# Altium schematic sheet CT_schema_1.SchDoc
size 690 x 636 mm
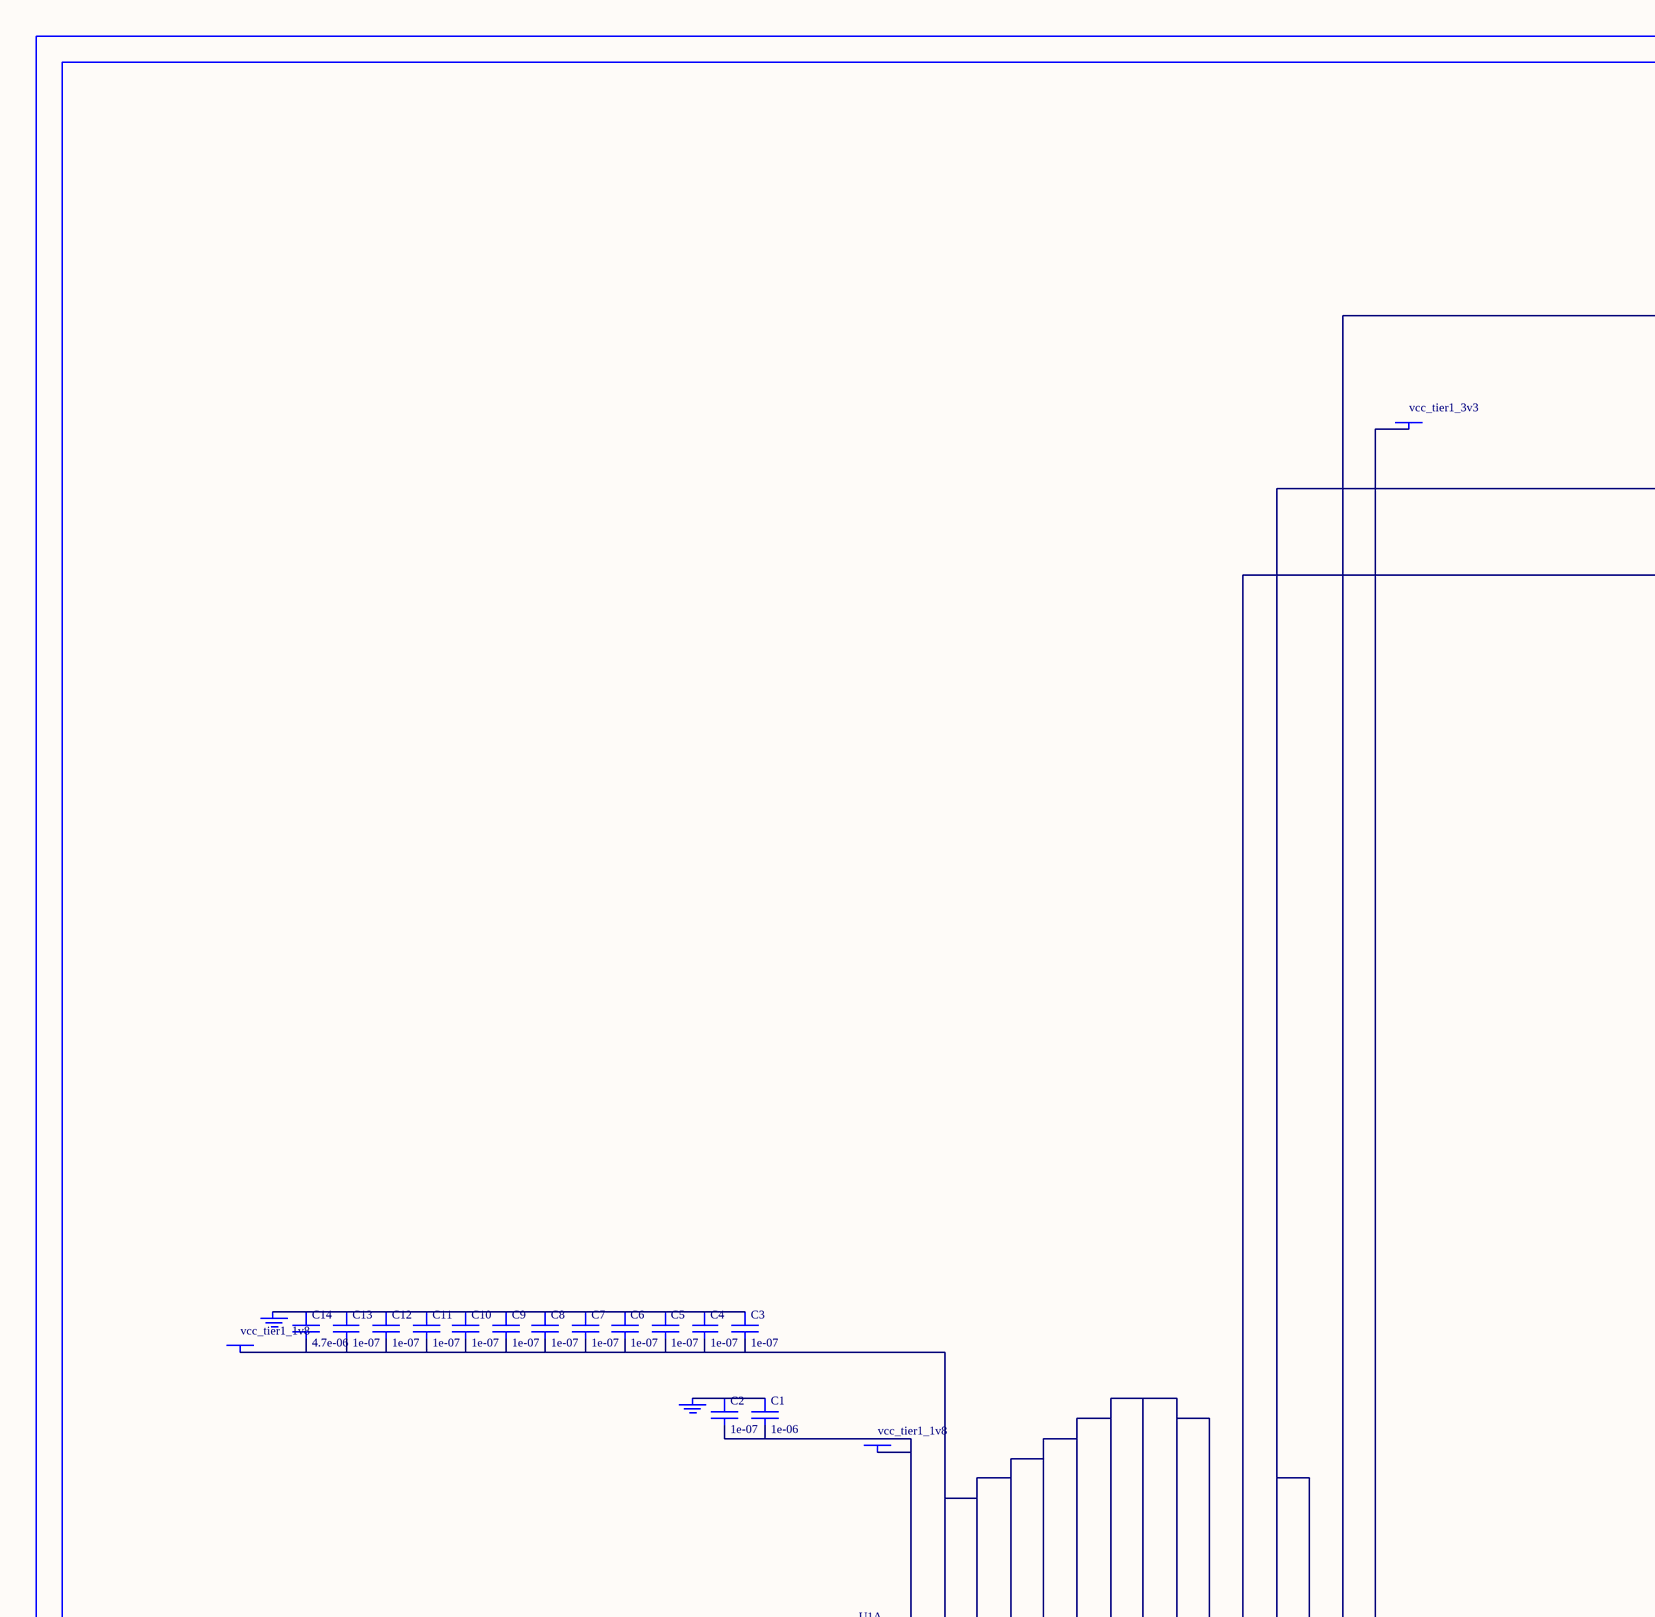
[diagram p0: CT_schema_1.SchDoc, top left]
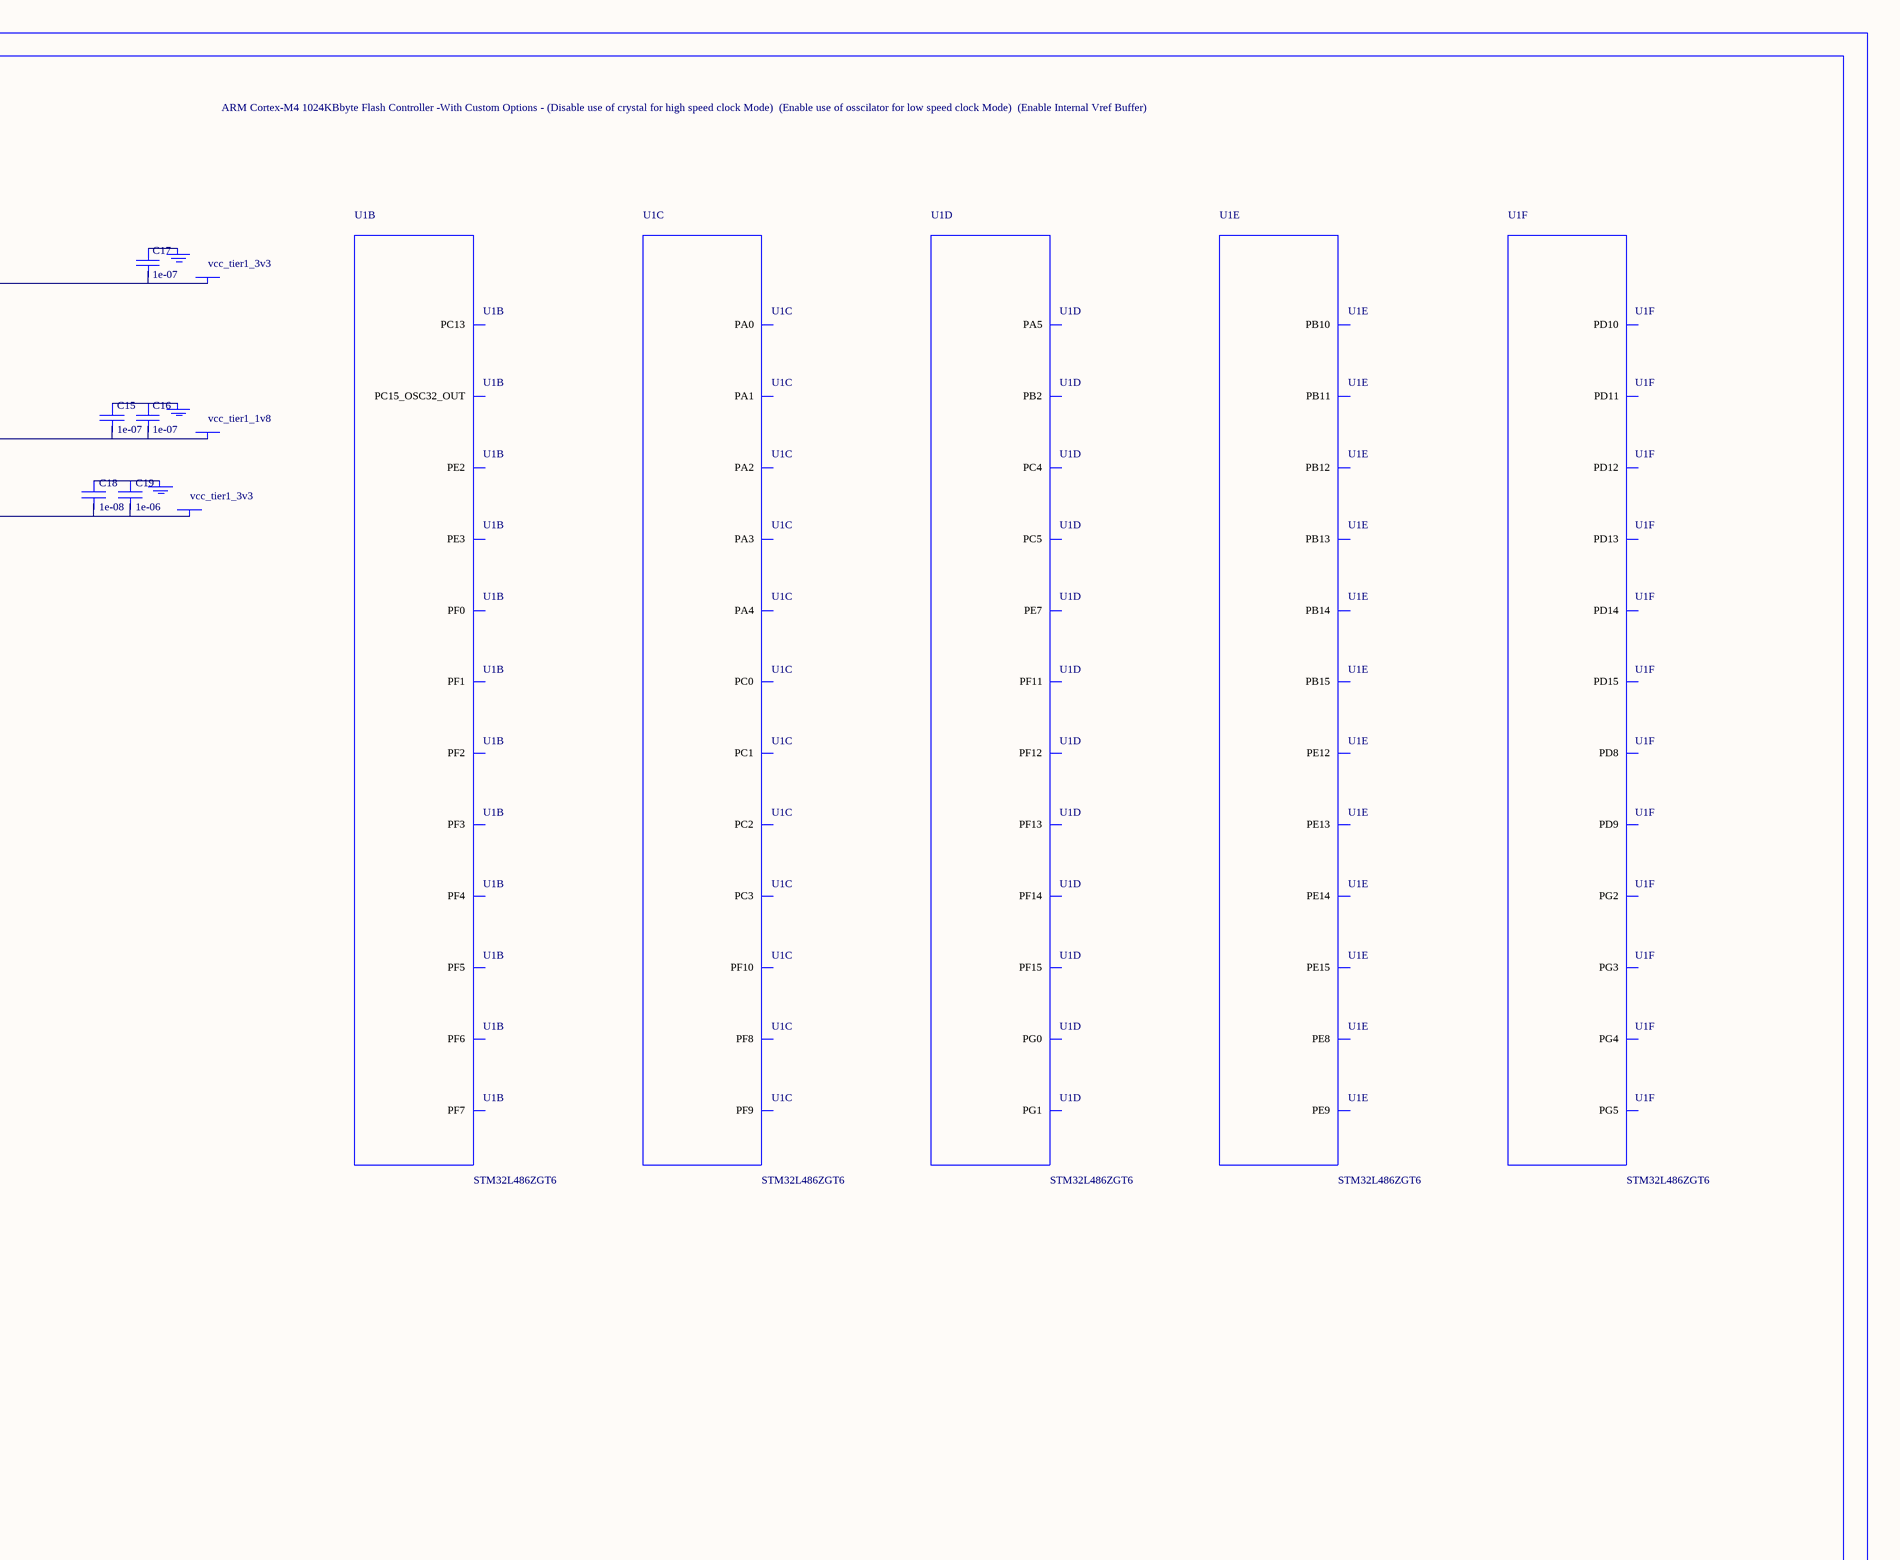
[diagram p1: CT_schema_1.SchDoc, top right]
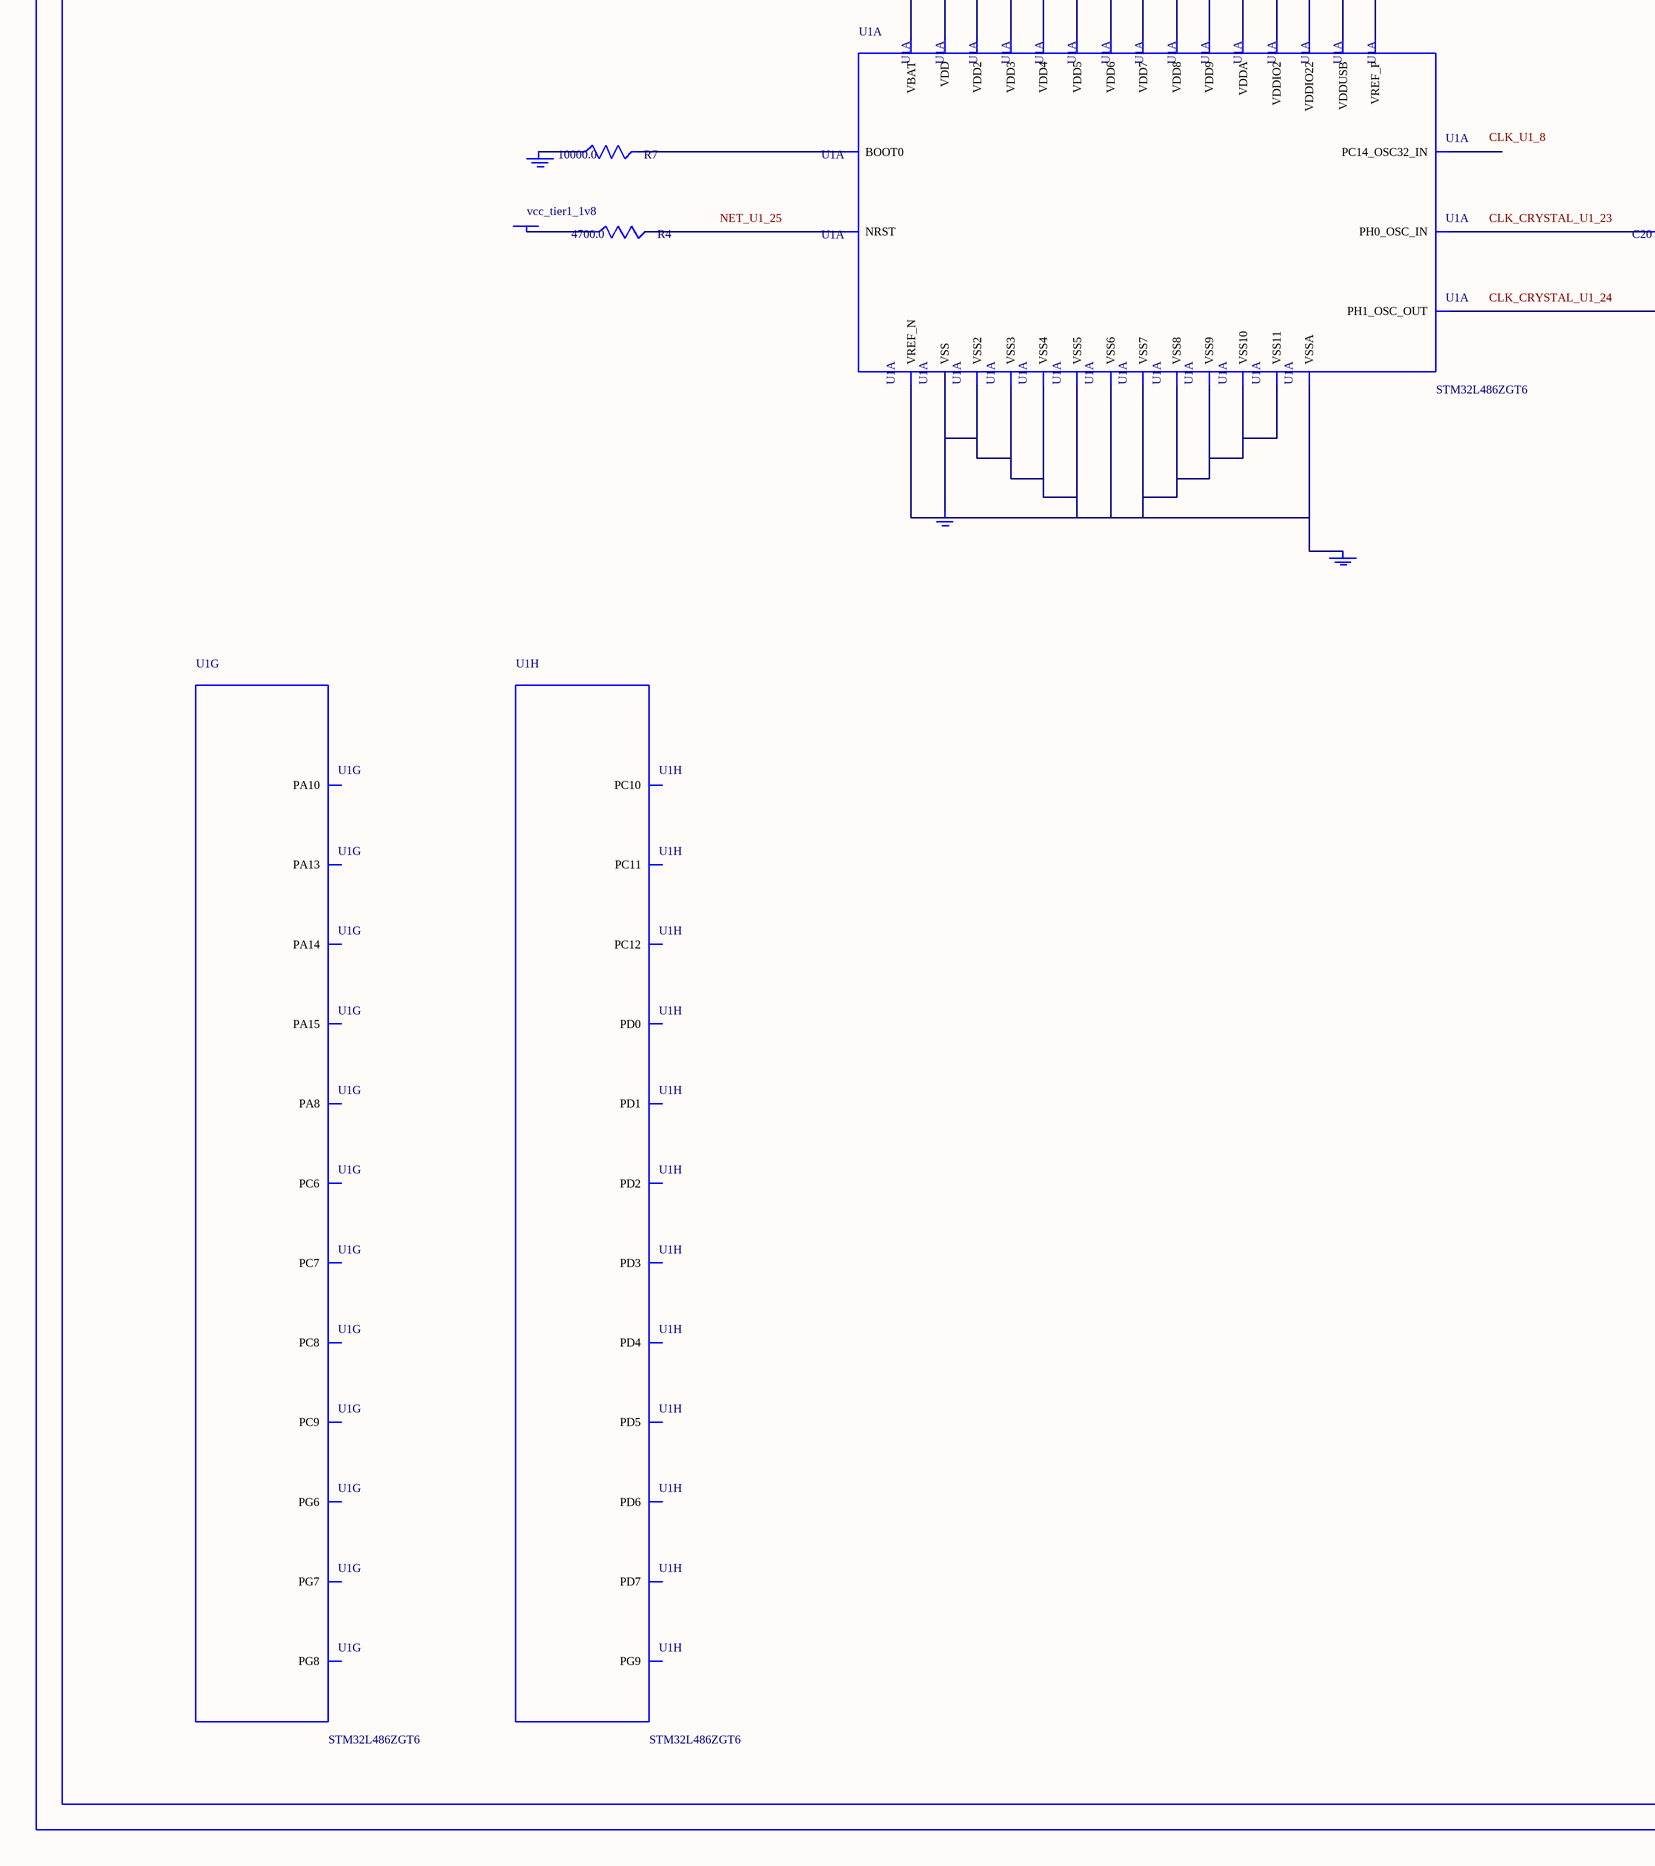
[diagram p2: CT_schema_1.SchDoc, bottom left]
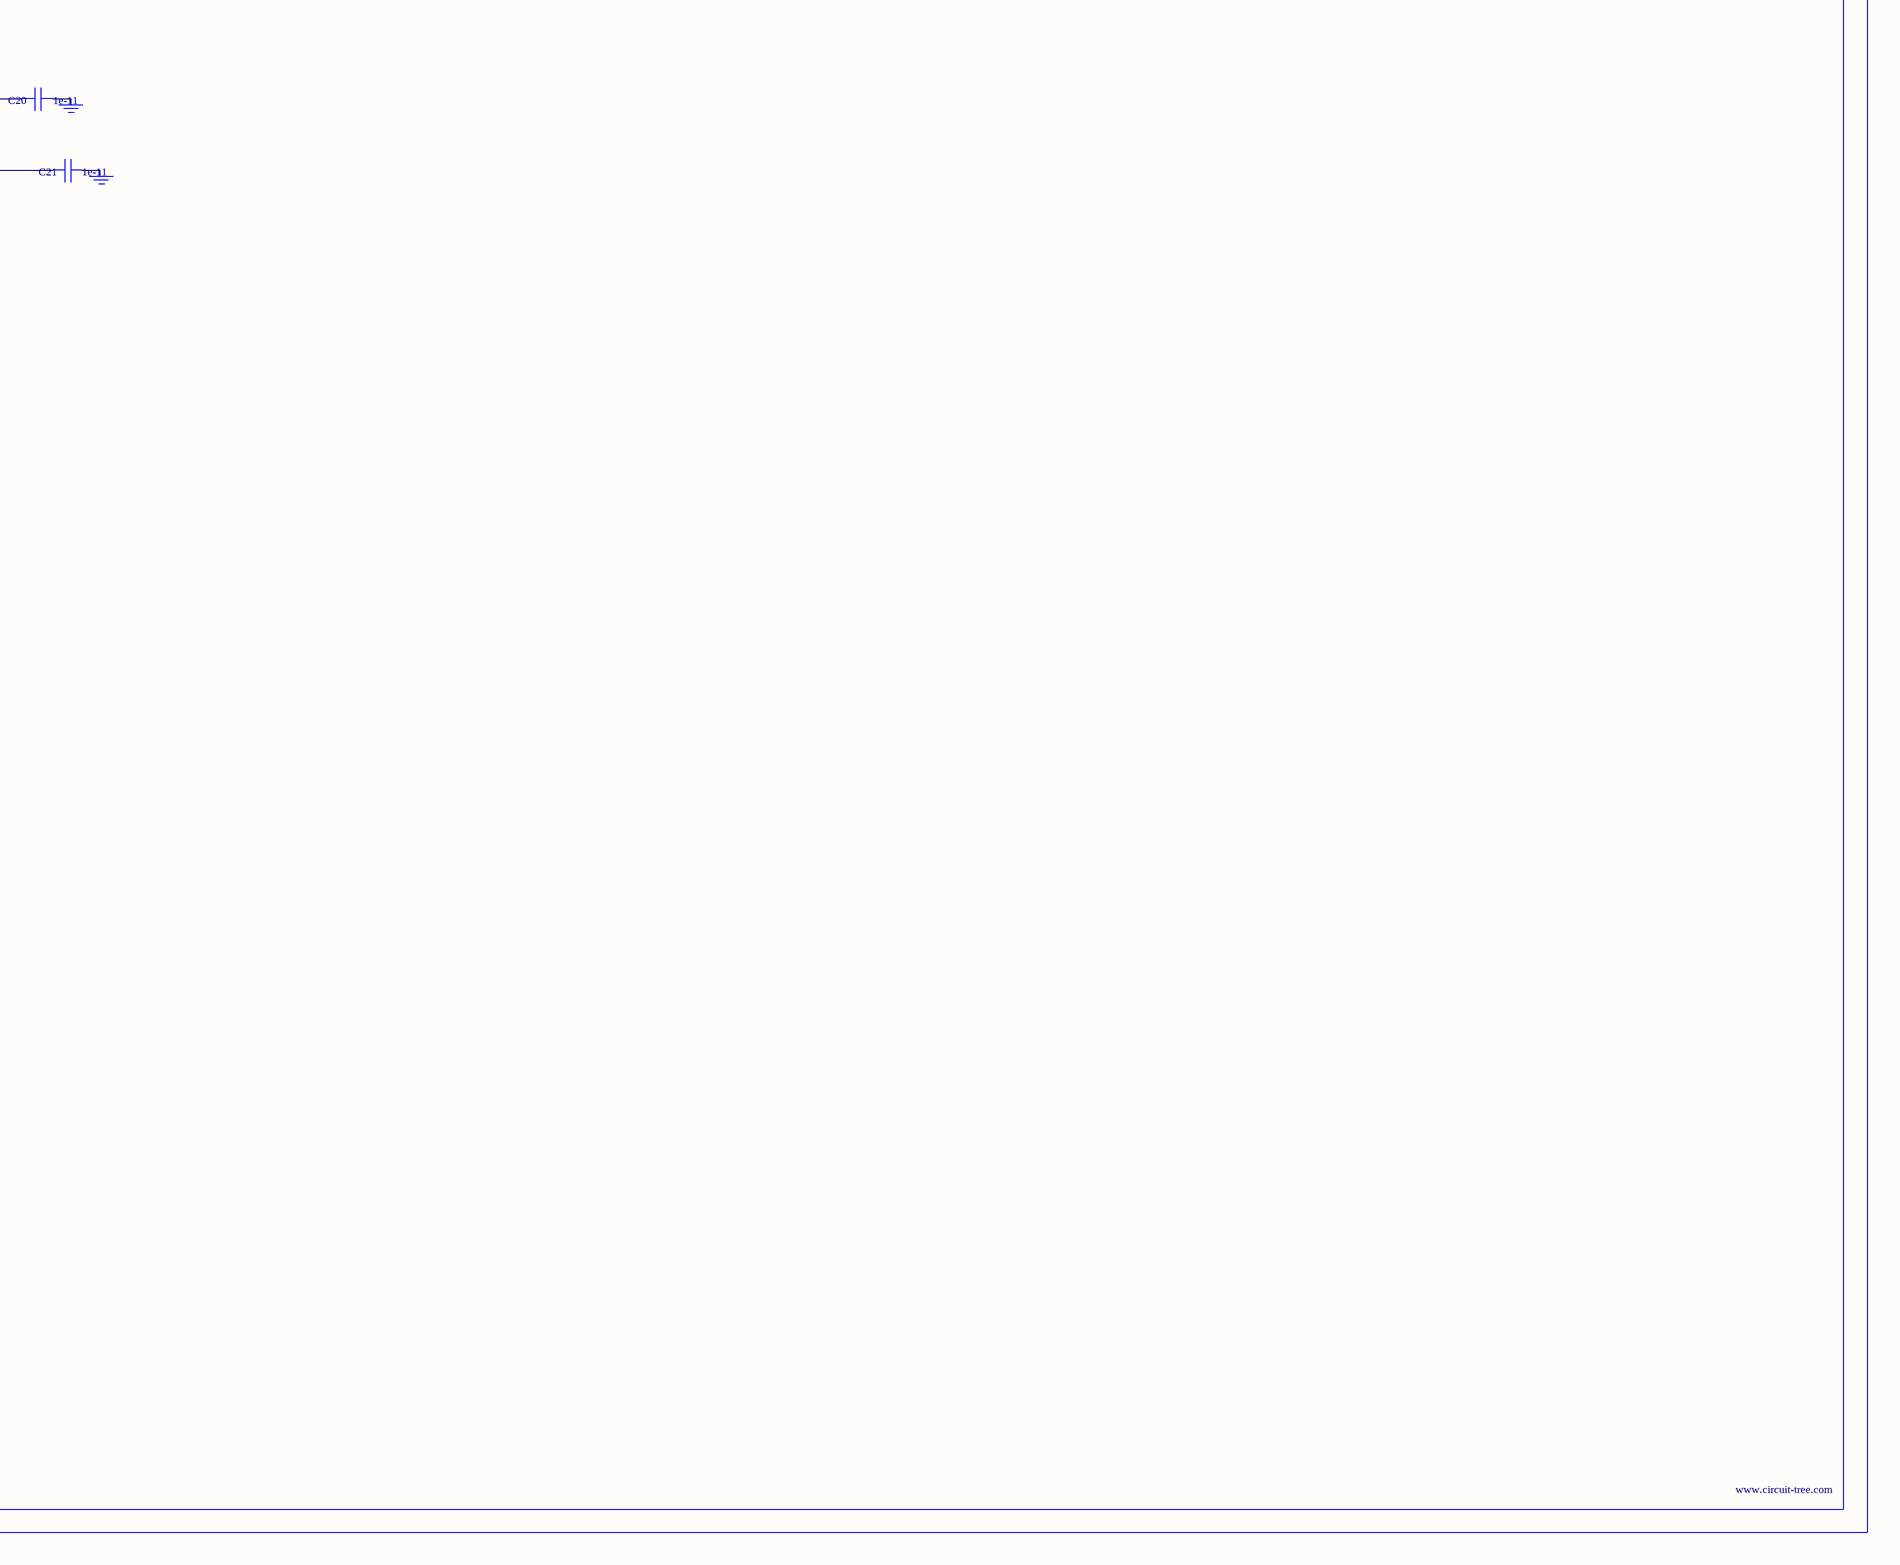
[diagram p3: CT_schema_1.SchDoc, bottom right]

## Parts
BORDER0  (no value)
C1  1e-06  [C0603]
C2  1e-07  [C0603]
C3  1e-07  [C0603]
C4  1e-07  [C0603]
C5  1e-07  [C0603]
C6  1e-07  [C0603]
C7  1e-07  [C0603]
C8  1e-07  [C0603]
C9  1e-07  [C0603]
C10  1e-07  [C0603]
C11  1e-07  [C0603]
C12  1e-07  [C0603]
C13  1e-07  [C0603]
C14  4.7e-06  [C0603]
C15  1e-07  [C0603]
C16  1e-07  [C0603]
C17  1e-07  [C0603]
C18  1e-08  [C0603]
C19  1e-06  [C0603]
C20  1e-11  [C0402]
C21  1e-11  [C0402]
GND_INSTANCE_0_0  (no value)
GND_INSTANCE_0_1  (no value)
GND_INSTANCE_0_2  (no value)
GND_INSTANCE_0_3  (no value)
GND_INSTANCE_0_4  (no value)
GND_INSTANCE_0_5  (no value)
GND_INSTANCE_0_6  (no value)
GND_INSTANCE_0_7  (no value)
GND_INSTANCE_0_8  (no value)
GND_INSTANCE_0_9  (no value)
POWER_INSTANCE_0_0  vcc_tier1_1v8
POWER_INSTANCE_0_1  vcc_tier1_1v8
POWER_INSTANCE_0_2  vcc_tier1_3v3
POWER_INSTANCE_0_3  vcc_tier1_3v3
POWER_INSTANCE_0_4  vcc_tier1_1v8
POWER_INSTANCE_0_5  vcc_tier1_3v3
POWER_INSTANCE_0_6  vcc_tier1_1v8
R4  4700.0  [R0603]
R7  10000.0  [R0603]
U1  STM32L486ZGT6  [LQFP144]  (parts A,B,C,D,E,F,G,H of 11)

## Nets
NetC1_1: C1.1 C2.1 GND_INSTANCE_0_0.0(GND)
NetC1_2: C1.2 C2.2 POWER_INSTANCE_0_0.0(PWR) U1.6(VBAT)
NetC3_1: C3.1 C4.1 C5.1 C6.1 C7.1 C8.1 C9.1 C10.1 C11.1 C12.1 C13.1 C14.1 GND_INSTANCE_0_1.0(GND)
NetC3_2: C3.2 C4.2 C5.2 C6.2 C7.2 C8.2 C9.2 C10.2 C11.2 C12.2 C13.2 C14.2 POWER_INSTANCE_0_1.0(PWR) U1.17(VDD) U1.39(VDD2) U1.52(VDD3) U1.62(VDD4) U1.72(VDD5) U1.84(VDD6) U1.108(VDD7) U1.121(VDD8) U1.144(VDD9)
NetC15_1: C15.1 C16.1 GND_INSTANCE_0_6.0(GND)
NetC15_2: C15.2 C16.2 POWER_INSTANCE_0_4.0(PWR) U1.95(VDDIO2) U1.131(VDDIO22)
NetC17_1: C17.1 GND_INSTANCE_0_7.0(GND)
NetC17_2: C17.2 POWER_INSTANCE_0_5.0(PWR) U1.106(VDDUSB)
NetC18_1: C18.1 C19.1 GND_INSTANCE_0_5.0(GND)
NetC18_2: C18.2 C19.2 POWER_INSTANCE_0_3.0(PWR) U1.33(VDDA)
NetC20_1: C20.1 GND_INSTANCE_0_2.0(GND)
NetC20_2: C20.2 U1.23(PH0_OSC_IN)
NetC21_1: C21.1 GND_INSTANCE_0_3.0(GND)
NetC21_2: C21.2 U1.24(PH1_OSC_OUT)
NetGND_INSTANCE_0_4_0: GND_INSTANCE_0_4.0(GND) GND_INSTANCE_0_9.0(GND) U1.16(VSS) U1.30(VSSA) U1.31(VREF_N) U1.38(VSS2) U1.51(VSS3) U1.61(VSS4) U1.71(VSS5) U1.83(VSS6) U1.94(VSS7) U1.107(VSS8) U1.120(VSS9) U1.130(VSS10) U1.143(VSS11)
NetGND_INSTANCE_0_8_0: GND_INSTANCE_0_8.0(GND) R7.1
NetPOWER_INSTANCE_0_2_0: POWER_INSTANCE_0_2.0(PWR) U1.32(VREF_P)
NetPOWER_INSTANCE_0_6_0: POWER_INSTANCE_0_6.0(PWR) R4.1
NetR4_2: R4.2 U1.25(NRST)
NetR7_2: R7.2 U1.138(BOOT0)

Not connected (* = marked no-connect by the designer): U1 1(PE2) 2(PE3) 7(PC13) 8(PC14_OSC32_IN) 9(PC15_OSC32_OUT) 10(PF0) 11(PF1) 12(PF2) 13(PF3) 14(PF4) 15(PF5) 18(PF6) 19(PF7) 20(PF8) 21(PF9) 22(PF10) 26(PC0) 27(PC1) 28(PC2) 29(PC3) 34(PA0) 35(PA1) 36(PA2) 37(PA3) 40(PA4) 41(PA5) 44(PC4) 45(PC5) 48(PB2) 49(PF11) 50(PF12) 53(PF13) 54(PF14) 55(PF15) 56(PG0) 57(PG1) 58(PE7) 59(PE8) 60(PE9) 65(PE12) 66(PE13) 67(PE14) 68(PE15) 69(PB10) 70(PB11) 73(PB12) 74(PB13) 75(PB14) 76(PB15) 77(PD8) 78(PD9) 79(PD10) 80(PD11) 81(PD12) 82(PD13) 85(PD14) 86(PD15) 87(PG2) 88(PG3) 89(PG4) 90(PG5) 91(PG6) 92(PG7) 93(PG8) 96(PC6) 97(PC7) 98(PC8) 99(PC9) 100(PA8) 102(PA10) 105(PA13) 109(PA14) 110(PA15) 111(PC10) 112(PC11) 113(PC12) 114(PD0) 115(PD1) 116(PD2) 117(PD3) 118(PD4) 119(PD5) 122(PD6) 123(PD7) 124(PG9)

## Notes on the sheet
- Labels drawn without touching a wire or pin: CLK_CRYSTAL_U1_23, CLK_CRYSTAL_U1_24, CLK_U1_8, NET_U1_25

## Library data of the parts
BORDER0 = BORDER_PAGE0
C1 C19 = C0603C105K3RACTU
C2-C13 C15-C17 = 06035C104K4Z2A
C14 = GRM188R6YA475KE15D
C18 = 06035C103K4Z2A
C20 C21 = C0402C100K3GACTU
GND_INSTANCE_0_0-GND_INSTANCE_0_9 = GND
POWER_INSTANCE_0_0-POWER_INSTANCE_0_6 = PWR
R4 = RC0603JR-074K7L
R7 = RC0603JR-0710KL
